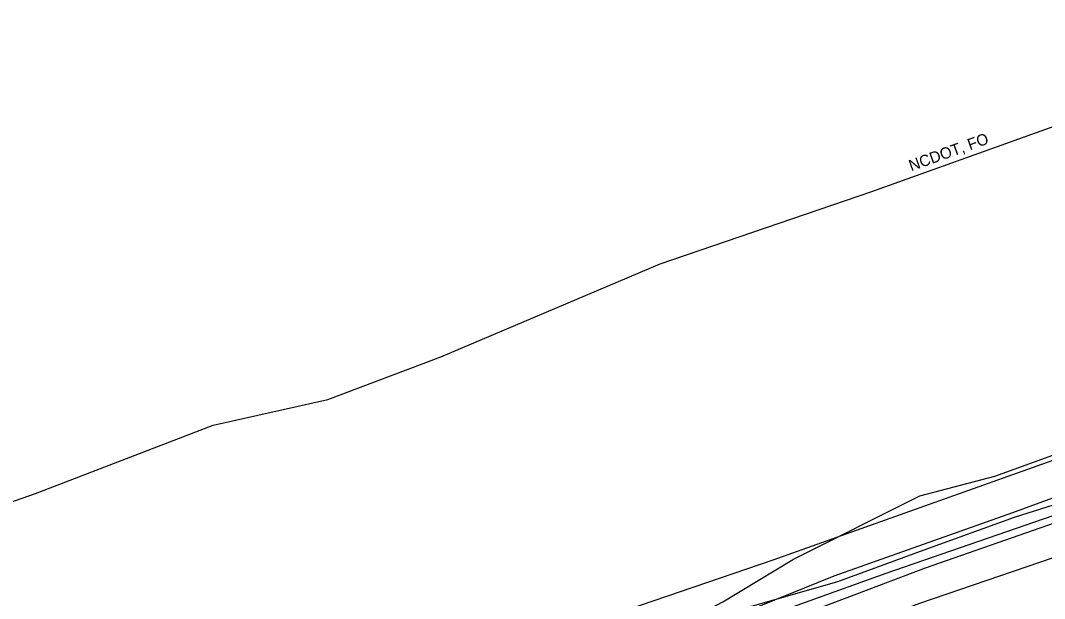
# Model space of a CAD drawing. Extents: x 2070721 to 2083340, y 729290 to 737883.
# Drawn here: x 2080183.4 to 2080544.7, y 734551.5 to 734755.4 of the extents above; entities that cross this region are included whole.
import ezdxf

# ---------------------------------------------------------------- set-up
doc = ezdxf.new("R2010")
doc.units = 0
for name, color, linetype in [('Exist Utilities Power UG Cable SUE LOS C', 7, 'Continuous'), ('Exist Utilities Telephone UG Cable SUE LOS C', 7, 'Continuous'), ('Exist Utilities Telephone UG Conduit SUE LOS B', 7, 'Continuous'), ('Exist Utilities Telephone UG FO SUE LOS B', 7, 'Continuous'), ('Exist Utilities Telephone UG FO SUE LOS B Text', 7, 'Continuous'), ('Exist Utilities Water UG Line SUE LOS B', 7, 'Continuous')]:
    doc.layers.add(name, color=color, linetype=linetype)

msp = doc.modelspace()

# ---------------------------------------------------------------- linework, layer by layer
at = {"layer": 'Exist Utilities Power UG Cable SUE LOS C'}
msp.add_lwpolyline([(2080186.05, 734475.29), (2080187.03, 734475.63), (2080448.94, 734565.1), (2080663.08, 734641.37), (2080827.26, 734699.95), (2080984.4, 734756.05), (2081109.44, 734801.16), (2081210.88, 734831.9), (2081586.98, 734944.46), (2081830.55, 735019.69), (2082038.54, 735143.44), (2082248.34, 735270.09)], dxfattribs=at)
at = {"layer": 'Exist Utilities Telephone UG Cable SUE LOS C'}
for points in [[(2080527.18, 734594.58), (2080756.63, 734677.7), (2080975.53, 734755.33), (2081114.85, 734806.49), (2081251.31, 734880.3), (2081357.91, 734934.96), (2081407.46, 734955.63), (2081557.34, 735013.56), (2081611.19, 735031.21), (2081670.8, 735036.79), (2081727.82, 735033.26), (2081796.62, 735020.83), (2081876.61, 734998.57), (2081913.61, 734982.12), (2081940.08, 734960.79), (2081955.36, 734908.6), (2081940.34, 734844.38), (2081917.15, 734795.51)], [(2080392.43, 734459.45), (2080392.18, 734455.98), (2080369.79, 734491.21), (2080371.64, 734506.16), (2080398.8, 734522.93), (2080423.1, 734536.76), (2080488.87, 734560.43), (2080551.19, 734581.93), (2080605.97, 734600.8), (2080683.17, 734629.37), (2080713.38, 734633.09), (2080745.42, 734609.78), (2080760.77, 734576.63), (2080781.91, 734561.06), (2080789.84, 734547.84), (2080795.45, 734523.96), (2080798.47, 734502.81), (2080795.45, 734476.11), (2080787.39, 734456.13)], [(2080389.44, 734455.05), (2080371.58, 734477.3), (2080359.8, 734497.02), (2080353.64, 734504.17), (2080362.14, 734509.13), (2080380.41, 734522.38), (2080412.54, 734540.56), (2080431.18, 734550.33), (2080456.15, 734565.37), (2080500.74, 734587.65), (2080527.18, 734594.58)]]:
    msp.add_lwpolyline(points, dxfattribs=at)
at = {"layer": 'Exist Utilities Telephone UG Conduit SUE LOS B'}
msp.add_lwpolyline([(2080232.24, 734245.67), (2080237.5, 734254.36), (2080238.66, 734282.35), (2080245.75, 734323.83), (2080258.86, 734369.55), (2080269.86, 734398.57), (2080309.08, 734449.32), (2080323.63, 734464.88), (2080355.41, 734492.16), (2080379.52, 734509.8), (2080416.03, 734529.49), (2080502.71, 734562.3), (2080573.96, 734587.12), (2080616.57, 734603.22), (2080677.16, 734624.99), (2080749, 734651.22), (2080815.57, 734674.3), (2080861.11, 734690.56), (2080923.26, 734714.15), (2080934.26, 734720.97)], dxfattribs=at)
at = {"layer": 'Exist Utilities Telephone UG FO SUE LOS B'}
for points in [[(2079745.48, 734481.51), (2079801.23, 734497.35), (2079872.83, 734508.05), (2079949.65, 734523.37), (2080020.61, 734534.5), (2080089.55, 734553.89), (2080188.62, 734588.57), (2080251.31, 734612.62), (2080291.78, 734621.68), (2080331.66, 734636.74), (2080409.13, 734669.6), (2080483.75, 734695.04), (2080565.61, 734724.43), (2080648.3, 734753.97), (2080723.36, 734781.19), (2080819.84, 734816.74), (2080898.17, 734842.61), (2080939.09, 734839.81), (2081012.97, 734869.95)], [(2080235.11, 734249.36), (2080234.94, 734252.48), (2080236.58, 734281.87), (2080244.62, 734323.58), (2080257.8, 734369.84), (2080268.59, 734399.28), (2080285.42, 734425.78), (2080306.49, 734446.52), (2080318.99, 734464.89), (2080332.07, 734479.26), (2080365.28, 734504.24), (2080415, 734536.31), (2080432.75, 734546.34), (2080471.85, 734557.5), (2080502.31, 734568.65), (2080534.18, 734580.2), (2080570.94, 734591.77), (2080576.66, 734593.81), (2080717.24, 734648.01)], [(2080228.28, 734243.43), (2080230.55, 734282.39), (2080237.1, 734324.84), (2080265.61, 734400.42), (2080300.19, 734451.55), (2080329.83, 734482.91), (2080380.99, 734522.11), (2080413.6, 734539.64), (2080433.63, 734544.47), (2080470.56, 734559.5), (2080533.58, 734581.77), (2080652.68, 734625.4)]]:
    msp.add_lwpolyline(points, dxfattribs=at)
at = {"layer": 'Exist Utilities Water UG Line SUE LOS B'}
msp.add_lwpolyline([(2080357.06, 734003.27), (2080353.32, 734006.79), (2080296.63, 734072.2), (2080261.95, 734141.13), (2080251.22, 734185.42), (2080250, 734189.2), (2080244.12, 734248.6), (2080244.13, 734251.5), (2080244.63, 734259.68), (2080245.13, 734264.1), (2080254.44, 734320.44), (2080276.53, 734380.91), (2080391.41, 734503.18), (2080497.9, 734548.7), (2080500.72, 734549.83), (2080585.45, 734578.7), (2080702.53, 734619.89), (2080710.17, 734622.62), (2080743.51, 734634.52), (2080754.26, 734638.28), (2080902.52, 734692.58), (2081024.44, 734735.33)], dxfattribs=at)

# ---------------------------------------------------------------- texts
at = {"layer": 'Exist Utilities Telephone UG FO SUE LOS B Text'}
msp.add_text('NCDOT, FO', height=4, rotation=19.7495, dxfattribs=at).set_placement((2080497.71, 734702.18))

doc.saveas('drawing.dxf')
